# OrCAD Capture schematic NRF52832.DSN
size A; title: nRF52832; rev: v0.1; note: 01
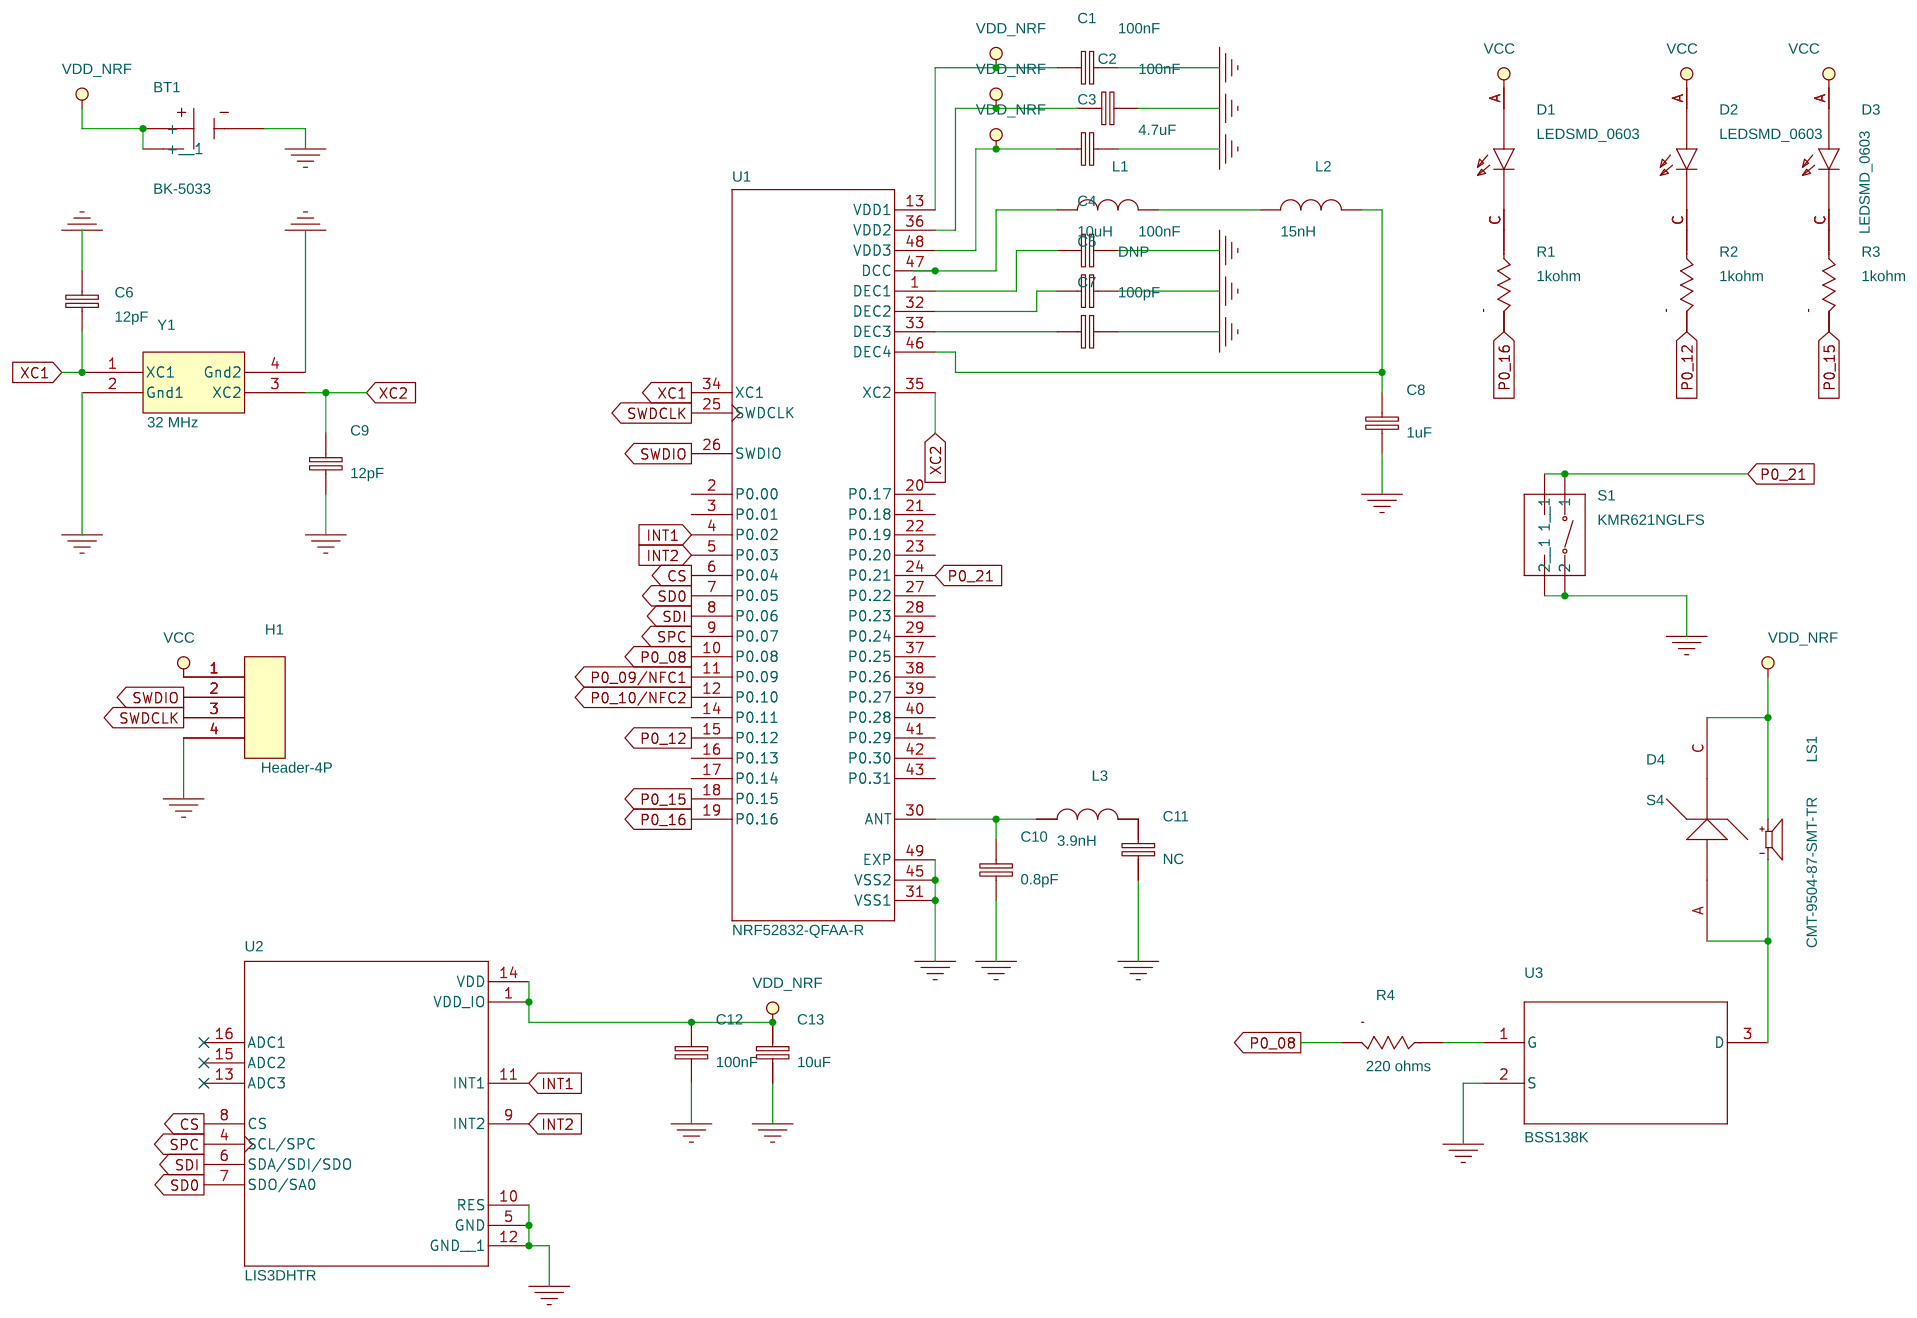
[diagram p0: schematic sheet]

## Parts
BT1  BK-5033  [BAT_BK-5033]
C1  100nF  [CAPC1005X55N]
C2  100nF  [CAPC1005X55N]
C3  4.7uF  [CAPC1005X55N]
C4  100nF  [CAPC1005X55N]
C5  DNP  [CAPC1005X55N]
C6  12pF  [CAPC1005X55N]
C7  100pF  [CAPC1005X55N]
C8  1uF  [CAPC1005X55N]
C9  12pF  [CAPC1005X55N]
C10  0.8pF  [CAPC1005X55N]
C11  NC  [CAPC1005X55N]
C12  100nF  [CAPC1005X55N]
C13  10uF  [CAPC1005X55N]
D1  LEDSMD_0603  [LEDM1608X80]
D2  LEDSMD_0603  [LEDM1608X80]
D3  LEDSMD_0603  [LEDM1608X80]
D4  S4  [SOD2513X120N]
H1  Header-4P  [4P_Header]
L1  10uH  [INDC1005X55N]
L2  15nH  [INDC1005X55N]
L3  3.9nH  [INDC1005X55N]
LS1  CMT-9504-87-SMT-TR  [XDCR_CMT-9504-87-SMT-TR]
R1  1kohm  [RESC1005X40N]
R2  1kohm  [RESC1005X40N]
R3  1kohm  [RESC1005X40N]
R4  220 ohms  [RESC1005X40N]
S1  KMR621NGLFS  [SW_KMR621NGLFS]
U1  NRF52832-QFAA-R  [QFN40P600X600X90-49N]
U2  LIS3DHTR  [XDCR_LIS3DHTR]
U3  BSS138K  [SOT95P240X110-3N]
Y1  32 MHz  [16MHz_Crystal_4pin]

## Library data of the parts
BT1 = Coin_Cell-CR2450-BK-5033
C1-C13 = Capacitor_0402
D1-D3 = LEDSMD_0603
D4 = Diode_Schottky_0805_S4
H1 = Header-4P
L1-L3 = Inductor_0402
LS1 = Buzzer_SMD_8.5x8.5x4
R1-R4 = Resistor_0402
S1 = Reset_Switch_Smd_KMR621NGLFS
U1 = NRF52832-QFAA-R
U2 = LIS3DHTR
U3 = BSS138K
Y1 = Crystal_Oscillator_32_MHz

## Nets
GND: BT1.- C1.2 C2.2 C3.2 C4.2 C5.2 C6.2 C7.2 C8.2 C9.2 C10.2 C11.2 C12.2 C13.2 H1.4 S1.2_1(2) S1.2_2(2__1) U1.31(VSS1) U1.45(VSS2) U1.49(EXP) U2.5(GND) U2.10(RES) U2.12(GND__1) U3.2(S) Y1.2(Gnd1) Y1.4(Gnd2)
VDD_nRF: BT1.S+1(+) BT1.S+2(+__1) C1.1 C2.1 C3.1 C12.1 C13.1 D1.A D2.A D3.A D4.C H1.1 LS1.P U1.13(VDD1) U1.36(VDD2) U1.48(VDD3) U2.1(VDD_IO) U2.14(VDD)
CS: U1.6(P0.04) U2.8(CS)
INT1: U1.4(P0.02) U2.11(INT1)
INT2: U1.5(P0.03) U2.9(INT2)
P0_08: R4.1 U1.10(P0.08)
P0_09/NFC1: U1.11(P0.09)
P0_10/NFC2: U1.12(P0.10)
P0_12: R2.1 U1.15(P0.12)
P0_15: R3.1 U1.18(P0.15)
P0_16: R1.1 U1.19(P0.16)
P0_21: S1.1_1(1) S1.1_2(1__1) U1.24(P0.21)
SD0: U1.7(P0.05) U2.7(SDO/SA0)
SDI: U1.8(P0.06) U2.6(SDA/SDI/SDO)
SPC: U1.9(P0.07) U2.4(SCL/SPC)
SWDCLK: H1.3 U1.25(SWDCLK)
SWDIO: H1.2 U1.26(SWDIO)
XC1: C6.1 U1.34(XC1) Y1.1(XC1)
XC2: C9.1 U1.35(XC2) Y1.3(XC2)
N01519: C10.1 L3.1 U1.30(ANT)
N09596: C4.1 U1.1(DEC1)
N09735: C5.1 U1.32(DEC2)
N10563: C7.1 U1.33(DEC3)
N12077: D4.A LS1.N U3.3(D)
N14036: L1.1 U1.47(DCC)
N14480: C8.1 L2.2 U1.46(DEC4)
N17584: L1.2 L2.1
N709599: R4.2 U3.1(G)
N709800: D3.C R3.2
N709801: D1.C R1.2
N709812: D2.C R2.2
N709816: C11.1 L3.2

Not connected (* = marked no-connect by the designer): U1 2(P0.00) 3(P0.01) 14(P0.11) 16(P0.13) 17(P0.14) 20(P0.17) 21(P0.18) 22(P0.19) 23(P0.20) 27(P0.22) 28(P0.23) 29(P0.24) 37(P0.25) 38(P0.26) 39(P0.27) 40(P0.28) 41(P0.29) 42(P0.30) 43(P0.31); U2 13(ADC3)* 15(ADC2)* 16(ADC1)*
